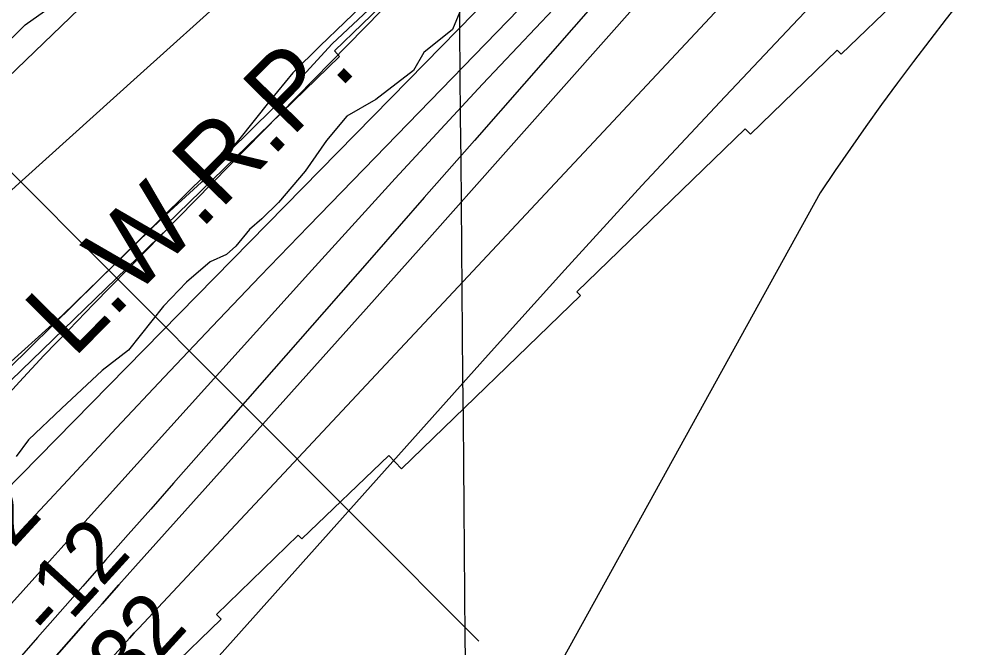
# Model space of a CAD drawing. Extents: x 3598634 to 3636690, y 517270 to 542944.
# Drawn here: x 3607559 to 3608618, y 532088 to 532774 of the extents above; entities that cross this region are included whole.
import ezdxf

# ---------------------------------------------------------------- set-up
doc = ezdxf.new("R2010")
doc.units = 0
for name, color, linetype in [('V-GRID-MAJR', 7, 'Continuous'), ('V-RIVR-EDGE', 7, 'Continuous'), ('V-RIVR-RANG', 7, 'Continuous'), ('V-RRAP-FSHR', 7, 'Continuous'), ('V-RRAP-RVMT', 7, 'Continuous'), ('V-SITE-VEGE', 7, 'Continuous'), ('V-TOPO-DPTH', 7, 'Continuous'), ('V-TOPO-MAJR', 7, 'Continuous'), ('V-TOPO-MINR', 7, 'Continuous'), ('V-TOPO-WATR', 7, 'Continuous'), ('V-TOPO-WATR-IDEN', 7, 'Continuous')]:
    doc.layers.add(name, color=color, linetype=linetype)

msp = doc.modelspace()

# ---------------------------------------------------------------- linework, layer by layer
at = {"layer": 'V-GRID-MAJR'}
msp.add_spline([(3608130.468, 522726.087), (3608075.829, 528784.895), (3608021.174, 534845.634), (3607966.518, 540906.389), (3607966.501, 540908.307)], degree=3, dxfattribs=at)
at = {"layer": 'V-RIVR-EDGE'}
msp.add_lwpolyline([(3608039.8334377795, 532782.3621644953), (3608031.8195518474, 532762.774714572), (3608000.508544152, 532737.7303281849), (3607989.431041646, 532718.1504537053), (3607948.299794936, 532686.390352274), (3607916.3927299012, 532668.0874374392), (3607894.269541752, 532641.7948780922), (3607870.9027259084, 532608.152669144), (3607842.0198851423, 532573.9113726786), (3607823.5942481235, 532556.1878492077), (3607810.085548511, 532544.5794381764), (3607795.3347362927, 532526.2341008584), (3607784.895713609, 532517.069007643), (3607767.1070413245, 532509.1475421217), (3607741.3181189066, 532487.1531365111), (3607716.131314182, 532460.8681526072), (3607678.0227766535, 532412.5569462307), (3607649.1702376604, 532390.5701160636), (3607604.9511329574, 532349.0140170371), (3607568.7156124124, 532314.7909016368), (3607555.190246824, 532296.4425341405)], dxfattribs=at)
at = {"layer": 'V-RIVR-RANG'}
msp.add_line((3607425.2557, 532731.8928000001), (3608060.9099, 532094.7558000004), dxfattribs=at)
at = {"layer": 'V-RRAP-FSHR'}
msp.add_lwpolyline([(3605820.86382512, 530227.3894172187), (3606036.061521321, 530488.3844894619), (3606189.2990254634, 530713.2835616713), (3606419.5761456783, 531040.6747939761), (3606531.1368497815, 531185.7858341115), (3606653.304145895, 531360.7157542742), (3606830.6076980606, 531571.9730984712), (3606913.7257781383, 531664.9400105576), (3606995.6908342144, 531767.9892266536), (3607074.1906742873, 531873.2789547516), (3607165.5724343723, 531981.5730988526), (3607230.9753144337, 532060.8941869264), (3607289.867602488, 532131.0136109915), (3607473.880402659, 532321.0700591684), (3607836.054866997, 532677.0083635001), (3607900.3948350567, 532747.1503155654), (3608145.0202432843, 532976.3297077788), (3608226.1701953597, 533101.7266998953), (3608431.6276035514, 533291.5517240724), (3608655.69928376, 533489.6629562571), (3608731.274579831, 533575.8530363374), (3608845.2990279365, 533667.1917884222), (3608960.3638600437, 533749.2674364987)], dxfattribs=at)
at = {"layer": 'V-RRAP-RVMT'}
for p, q in [((3608003.6540000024, 532836.841), (3607902.9160000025, 532739.5930000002)), ((3608456.6170000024, 532735.9100000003), (3608557.1770000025, 532833.0250000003)), ((3607902.9160000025, 532739.5930000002), (3607908.6820000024, 532733.4860000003)), ((3608357.5000000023, 532648.7180000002), (3608452.292000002, 532740.4)), ((3608452.292000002, 532740.4), (3608456.6170000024, 532735.9100000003)), ((3607908.6820000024, 532733.4860000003), (3607719.1890000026, 532549.6730000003)), ((3608167.7370000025, 532476.4890000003), (3608351.7340000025, 532654.465)), ((3608351.7340000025, 532654.465), (3608357.5000000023, 532648.7180000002)), ((3607721.892000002, 532546.8000000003), (3607538.1650000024, 532368.5090000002)), ((3607719.1890000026, 532549.6730000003), (3607721.892000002, 532546.8000000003)), ((3607976.3520000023, 532283.067), (3608171.702000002, 532472.5380000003)), ((3608171.702000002, 532472.5380000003), (3608167.737000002, 532476.4890000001)), ((3607867.5030000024, 532206.561), (3607962.2950000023, 532297.794)), ((3607962.2950000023, 532297.794), (3607976.3520000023, 532283.067)), ((3607774.1530000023, 532124.1270000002), (3607863.539000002, 532210.5120000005)), ((3607863.5390000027, 532210.5120000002), (3607867.503000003, 532206.5610000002)), ((3607779.1990000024, 532118.7390000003), (3607774.1530000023, 532124.1270000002)), ((3607678.2800000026, 532021.8490000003), (3607779.1990000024, 532118.7390000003))]:
    msp.add_line(p, q, dxfattribs=at)
at = {"layer": 'V-SITE-VEGE'}
for p, q in [((3607945.514, 532801.16), (3607914.086, 532770.606)), ((3607565.1520000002, 532768.116), (3607598.649, 532791.698)), ((3607914.086, 532770.606), (3607887.548, 532744.914)), ((3607535.12, 532738.9500000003), (3607565.1520000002, 532768.116)), ((3607887.548, 532744.914), (3607857.518, 532715.748)), ((3607857.518, 532715.748), (3607832.358, 532685.174)), ((3607832.358, 532685.174), (3607798.107, 532642.088)), ((3607798.107, 532642.088), (3607757.582, 532596.2390000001)), ((3607757.582, 532596.2390000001), (3607714.289, 532556.6640000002)), ((3607714.289, 532556.6640000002), (3607606.038, 532451.11)), ((3607606.038, 532451.11), (3607511.074, 532365.7140000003))]:
    msp.add_line(p, q, dxfattribs=at)
at = {"layer": 'V-TOPO-DPTH'}
for points in [[(3609278.5001712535, 533933.5956766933), (3608503.449095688, 533229.7901084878), (3608489.255443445, 533216.7930610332), (3608475.13462605, 533203.7180066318), (3608461.123060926, 533190.5259418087), (3608447.1843306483, 533177.2558700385), (3608433.357443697, 533163.8693486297), (3608419.6068220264, 533150.4055932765), (3608405.9705982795, 533136.8259870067), (3608392.4106398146, 533123.1691467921), (3608273.992108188, 533002.8911629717), (3608201.2971241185, 532929.0206530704), (3608128.6248490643, 532855.1278195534), (3608055.986637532, 532781.2015006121), (3607983.3711350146, 532707.2528580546), (3607541.4783495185, 532257.0399294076)], [(3607541.4783495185, 532257.0399294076), (3607983.3711350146, 532707.2528580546), (3608055.986637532, 532781.2015006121), (3608128.6248490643, 532855.1278195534), (3608201.2971241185, 532929.0206530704), (3608273.992108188, 533002.8911629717), (3608392.4106398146, 533123.1691467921), (3608405.9705982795, 533136.8259870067), (3608419.6068220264, 533150.4055932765), (3608433.357443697, 533163.8693486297), (3608447.1843306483, 533177.2558700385), (3608461.123060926, 533190.5259418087), (3608475.13462605, 533203.7180066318), (3608489.255443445, 533216.7930610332), (3608503.449095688, 533229.7901084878), (3609278.5001712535, 533933.5956766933)], [(3609282.584963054, 533874.5401358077), (3609091.247997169, 533702.7828415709), (3608983.6299711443, 533605.3252450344), (3608876.5858531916, 533507.24674469), (3608770.4025973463, 533408.2368886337), (3608664.7932495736, 533308.6061287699), (3608480.8088173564, 533133.5119626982), (3608467.6981051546, 533120.8858505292), (3608454.6885765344, 533108.1575379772), (3608441.830823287, 533095.2759248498), (3608429.07425362, 533082.2921113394), (3608258.604894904, 532906.7165803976), (3608161.2610271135, 532805.3337141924), (3608064.678899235, 532703.2382364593), (3607969.2393812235, 532600.073841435), (3607874.5616031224, 532496.1968348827), (3607613.8797606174, 532206.9684789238), (3607604.307241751, 532196.3432368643), (3607594.737684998, 532185.7153287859), (3607585.1725714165, 532175.0834216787), (3607575.610419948, 532164.4488485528), (3607441.354665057, 532015.0731620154)], [(3607441.354665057, 532015.0731620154), (3607575.610419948, 532164.4488485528), (3607585.1725714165, 532175.0834216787), (3607594.737684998, 532185.7153287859), (3607604.307241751, 532196.3432368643), (3607613.8797606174, 532206.9684789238), (3607874.5616031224, 532496.1968348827), (3607969.2393812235, 532600.073841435), (3608064.678899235, 532703.2382364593), (3608161.2610271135, 532805.3337141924), (3608258.604894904, 532906.7165803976), (3608429.07425362, 533082.2921113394), (3608441.830823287, 533095.2759248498), (3608454.6885765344, 533108.1575379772), (3608467.6981051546, 533120.8858505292), (3608480.8088173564, 533133.5119626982), (3608664.7932495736, 533308.6061287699), (3608770.4025973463, 533408.2368886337), (3608876.5858531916, 533507.24674469), (3608983.6299711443, 533605.3252450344), (3609091.247997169, 533702.7828415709), (3609282.584963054, 533874.5401358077)], [(3607761.756536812, 532061.8420105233), (3608070.940006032, 532407.7299699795), (3608154.5565031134, 532500.3363408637), (3608238.7840992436, 532592.3778493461), (3608323.9283439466, 532683.5720642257), (3608409.683687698, 532774.2014167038), (3608556.8758265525, 532928.2087829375), (3608569.5447898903, 532941.360415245), (3608582.2820881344, 532954.4450010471), (3608595.1218887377, 532967.4290170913), (3608608.030024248, 532980.3459866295), (3608754.478214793, 533125.7464296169), (3608840.7671019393, 533211.2062921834), (3608927.1965175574, 533296.5234415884), (3609013.836725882, 533381.6265212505), (3609100.617462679, 533466.5868877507), (3609393.7700248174, 533752.880796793)], [(3609393.7700248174, 533752.880796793), (3609100.617462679, 533466.5868877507), (3609013.836725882, 533381.6265212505), (3608927.1965175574, 533296.5234415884), (3608840.7671019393, 533211.2062921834), (3608754.478214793, 533125.7464296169), (3608608.030024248, 532980.3459866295), (3608595.1218887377, 532967.4290170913), (3608582.2820881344, 532954.4450010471), (3608569.5447898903, 532941.360415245), (3608556.8758265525, 532928.2087829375), (3608409.683687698, 532774.2014167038), (3608323.9283439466, 532683.5720642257), (3608238.7840992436, 532592.3778493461), (3608154.5565031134, 532500.3363408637), (3608070.940006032, 532407.7299699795), (3607761.756536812, 532061.8420105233)], [(3608839.0191137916, 533729.2974036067), (3608745.7274825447, 533650.5465240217), (3608653.111874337, 533570.9841752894), (3608356.299991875, 533312.6389762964), (3608335.6224398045, 533294.5466827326), (3608315.0079304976, 533276.3832125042), (3608294.487985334, 533258.112977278), (3608274.031082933, 533239.7715653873), (3608105.7390647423, 533088.0931887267), (3608001.1778853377, 532993.8653662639), (3607896.609302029, 532899.6457619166), (3607792.029612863, 532805.4384847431), (3607687.4425197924, 532711.2394256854), (3607394.9798662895, 532447.8566238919)], [(3607647.456580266, 532062.7259102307), (3607679.1488233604, 532098.3119338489), (3607681.625337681, 532101.072114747), (3607684.1153446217, 532103.8199780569), (3607686.6255904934, 532106.549364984), (3607689.1493289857, 532109.266434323), (3608392.4391153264, 532860.8429781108), (3608416.085211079, 532886.0312727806), (3608439.7851179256, 532911.1686698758), (3608463.565741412, 532936.2297206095), (3608487.4001759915, 532961.2398737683), (3608528.203715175, 533003.9185721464), (3608531.6913557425, 533007.5368427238), (3608535.198481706, 533011.1359705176), (3608538.7348357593, 533014.7063841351), (3608542.2906752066, 533018.2576549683), (3608858.5155658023, 533331.5116326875), (3608943.9548586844, 533415.5280905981), (3609029.8023927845, 533499.1222068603), (3609116.262288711, 533582.0828106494), (3609203.1304258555, 533664.6210727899)], [(3609203.1304258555, 533664.6210727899), (3609116.262288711, 533582.0828106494), (3609029.8023927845, 533499.1222068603), (3608943.9548586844, 533415.5280905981), (3608858.5155658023, 533331.5116326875), (3608542.2906752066, 533018.2576549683), (3608538.7348357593, 533014.7063841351), (3608535.198481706, 533011.1359705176), (3608531.6913557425, 533007.5368427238), (3608528.203715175, 533003.9185721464), (3608487.4001759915, 532961.2398737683), (3608463.565741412, 532936.2297206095), (3608439.7851179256, 532911.1686698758), (3608416.085211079, 532886.0312727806), (3608392.4391153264, 532860.8429781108), (3607689.1493289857, 532109.266434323), (3607686.6255904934, 532106.549364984), (3607684.1153446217, 532103.8199780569), (3607681.625337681, 532101.072114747), (3607679.1488233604, 532098.3119338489), (3607647.456580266, 532062.7259102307)], [(3607295.3812890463, 531733.6500398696), (3607612.8538788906, 532094.702802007), (3607631.004029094, 532115.2799605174), (3607649.196633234, 532135.8193981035), (3607667.4529182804, 532156.3022543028), (3607685.7516572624, 532176.7473895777), (3607793.558679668, 532296.824284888), (3607865.7218247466, 532377.3428985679), (3607937.7903754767, 532457.9459410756), (3608009.7170346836, 532538.6756268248), (3608081.549099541, 532619.489741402), (3608462.5011577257, 533048.8368106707), (3608473.26961942, 533060.8162101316), (3608484.1400110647, 533072.7011623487), (3608495.1632976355, 533084.4444437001), (3608506.2885141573, 533096.0932778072), (3608517.5682551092, 533107.5921858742), (3608528.952013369, 533118.9857228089), (3608540.491797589, 533130.2212030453), (3608552.1355991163, 533141.3513121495), (3608629.667054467, 533214.445897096)], [(3608629.667054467, 533214.445897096), (3608552.1355991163, 533141.3513121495), (3608540.491797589, 533130.2212030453), (3608528.952013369, 533118.9857228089), (3608517.5682551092, 533107.5921858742), (3608506.2885141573, 533096.0932778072), (3608495.1632976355, 533084.4444437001), (3608484.1400110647, 533072.7011623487), (3608473.26961942, 533060.8162101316), (3608462.5011577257, 533048.8368106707), (3608081.549099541, 532619.489741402), (3608009.7170346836, 532538.6756268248), (3607937.7903754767, 532457.9459410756), (3607865.7218247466, 532377.3428985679), (3607793.558679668, 532296.824284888), (3607685.7516572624, 532176.7473895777), (3607667.4529182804, 532156.3022543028), (3607649.196633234, 532135.8193981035), (3607631.004029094, 532115.2799605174), (3607612.8538788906, 532094.702802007), (3607295.3812890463, 531733.6500398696)]]:
    msp.add_lwpolyline(points, dxfattribs=at)
at = {"layer": 'V-TOPO-MAJR'}
msp.add_lwpolyline([(3609300.3634407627, 533552.8491525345), (3609016.7187628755, 533269.8300182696), (3608953.5202149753, 533205.6550992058), (3608891.086745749, 533140.7569662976), (3608829.8008945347, 533074.774012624), (3608769.280121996, 533008.0678451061), (3608670.142443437, 532896.8536778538), (3608659.874806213, 532885.1195735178), (3608649.7538251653, 532873.2626004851), (3608639.852828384, 532861.2213244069), (3608630.0984877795, 532849.0571796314), (3608571.473402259, 532774.5537446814), (3608553.4615599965, 532751.3866396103), (3608535.631783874, 532728.081917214), (3608518.0751069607, 532704.57076883), (3608500.7004961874, 532680.9220031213), (3608483.6076753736, 532657.06900385), (3608466.708385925, 532633.0813991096), (3608450.0993935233, 532608.8918861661), (3608433.683932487, 532584.5677677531), (3608012.1101972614, 531821.0103381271)], dxfattribs=at)
at = {"layer": 'V-TOPO-MINR'}
for points in [[(3609223.915346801, 533954.599584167), (3608737.174201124, 533540.4757134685), (3608674.837619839, 533486.6816043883), (3608613.0130186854, 533432.313459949), (3608551.956387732, 533377.084262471), (3608491.411736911, 533321.2810296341), (3608419.962379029, 533254.4950059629), (3608395.679328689, 533231.4976100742), (3608371.599880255, 533208.2916932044), (3608347.8258346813, 533184.7729948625), (3608324.2553910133, 533161.0457755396), (3607639.99524579, 532463.1694893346), (3607612.6995803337, 532435.0413486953), (3607585.599964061, 532406.727498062), (3607558.7944215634, 532378.1350824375), (3607532.184928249, 532349.3569568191)], [(3609282.584963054, 533874.5401358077), (3609091.247997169, 533702.7828415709), (3608983.6299711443, 533605.3252450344), (3608876.5858531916, 533507.24674469), (3608770.4025973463, 533408.2368886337), (3608664.7932495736, 533308.6061287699), (3608480.8088173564, 533133.5119626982), (3608467.6981051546, 533120.8858505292), (3608454.6885765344, 533108.1575379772), (3608441.830823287, 533095.2759248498), (3608429.07425362, 533082.2921113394), (3608258.604894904, 532906.7165803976), (3608161.2610271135, 532805.3337141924), (3608064.678899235, 532703.2382364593), (3607969.2393812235, 532600.073841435), (3607874.5616031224, 532496.1968348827), (3607613.8797606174, 532206.9684789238), (3607604.307241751, 532196.3432368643), (3607594.737684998, 532185.7153287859), (3607585.1725714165, 532175.0834216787), (3607575.610419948, 532164.4488485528), (3607441.354665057, 532015.0731620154)], [(3609251.8750106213, 533877.2427907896), (3608801.855911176, 533470.5025605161), (3608740.332455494, 533414.403539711), (3608679.1407860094, 533357.9480489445), (3608618.44679582, 533300.9578532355), (3608558.0845918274, 533243.6111875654), (3608482.8802259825, 533171.5334969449), (3608460.4882515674, 533149.8383593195), (3608438.255117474, 533127.9833756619), (3608416.2602438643, 533105.8886229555), (3608394.424210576, 533083.6340242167), (3607874.7256928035, 532548.1976372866), (3607821.8964364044, 532493.4515041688), (3607769.28043001, 532438.5023588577), (3607716.9842986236, 532383.2486952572), (3607664.901417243, 532327.7920194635), (3607611.74496276, 532270.861981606), (3607586.4297840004, 532243.6906844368), (3607561.1539720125, 532216.482895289), (3607535.9372101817, 532189.2203681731)], [(3608790.558722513, 533765.498688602), (3608689.947779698, 533689.3136096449), (3608589.7578000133, 533612.5677614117), (3608294.128591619, 533384.153739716), (3608273.339258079, 533367.8779649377), (3608252.691174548, 533351.4272065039), (3608232.254966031, 533334.7139725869), (3608211.960007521, 533317.8257550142), (3608092.2310816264, 533216.8931201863), (3608012.8650134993, 533148.6439975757), (3607934.4146307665, 533079.3780470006), (3607857.3377761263, 533008.5868544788), (3607781.17660688, 532936.7788339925), (3607320.225775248, 532493.5546481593)], [(3609393.7700248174, 533752.880796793), (3609100.617462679, 533466.5868877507), (3609013.836725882, 533381.6265212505), (3608927.1965175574, 533296.5234415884), (3608840.7671019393, 533211.2062921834), (3608754.478214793, 533125.7464296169), (3608608.030024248, 532980.3459866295), (3608595.1218887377, 532967.4290170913), (3608582.2820881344, 532954.4450010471), (3608569.5447898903, 532941.360415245), (3608556.8758265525, 532928.2087829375), (3608409.683687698, 532774.2014167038), (3608323.9283439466, 532683.5720642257), (3608238.7840992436, 532592.3778493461), (3608154.5565031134, 532500.3363408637), (3608070.940006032, 532407.7299699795), (3607761.756536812, 532061.8420105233)], [(3608839.0191137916, 533729.2974036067), (3608745.7274825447, 533650.5465240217), (3608653.111874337, 533570.9841752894), (3608356.299991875, 533312.6389762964), (3608335.6224398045, 533294.5466827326), (3608315.0079304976, 533276.3832125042), (3608294.487985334, 533258.112977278), (3608274.031082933, 533239.7715653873), (3608105.7390647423, 533088.0931887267), (3608001.1778853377, 532993.8653662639), (3607896.609302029, 532899.6457619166), (3607792.029612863, 532805.4384847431), (3607687.4425197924, 532711.2394256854), (3607394.9798662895, 532447.8566238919)], [(3609203.1304258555, 533664.6210727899), (3609116.262288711, 533582.0828106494), (3609029.8023927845, 533499.1222068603), (3608943.9548586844, 533415.5280905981), (3608858.5155658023, 533331.5116326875), (3608542.2906752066, 533018.2576549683), (3608538.7348357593, 533014.7063841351), (3608535.198481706, 533011.1359705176), (3608531.6913557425, 533007.5368427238), (3608528.203715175, 533003.9185721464), (3608487.4001759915, 532961.2398737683), (3608463.565741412, 532936.2297206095), (3608439.7851179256, 532911.1686698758), (3608416.085211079, 532886.0312727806), (3608392.4391153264, 532860.8429781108), (3607689.1493289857, 532109.266434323), (3607686.6255904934, 532106.549364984), (3607684.1153446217, 532103.8199780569), (3607681.625337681, 532101.072114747), (3607679.1488233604, 532098.3119338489), (3607647.456580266, 532062.7259102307)], [(3608629.667054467, 533214.445897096), (3608552.1355991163, 533141.3513121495), (3608540.491797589, 533130.2212030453), (3608528.952013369, 533118.9857228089), (3608517.5682551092, 533107.5921858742), (3608506.2885141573, 533096.0932778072), (3608495.1632976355, 533084.4444437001), (3608484.1400110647, 533072.7011623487), (3608473.26961942, 533060.8162101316), (3608462.5011577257, 533048.8368106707), (3608081.549099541, 532619.489741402), (3608009.7170346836, 532538.6756268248), (3607937.7903754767, 532457.9459410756), (3607865.7218247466, 532377.3428985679), (3607793.558679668, 532296.824284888), (3607685.7516572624, 532176.7473895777), (3607667.4529182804, 532156.3022543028), (3607649.196633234, 532135.8193981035), (3607631.004029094, 532115.2799605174), (3607612.8538788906, 532094.702802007), (3607295.3812890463, 531733.6500398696)], [(3608218.9489783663, 532827.5558370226), (3608055.9154751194, 532641.77406112), (3608001.142761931, 532579.3545981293), (3607946.3728539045, 532516.9326740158), (3607891.6071536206, 532454.5070582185), (3607836.8442584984, 532392.0789812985), (3607776.6746080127, 532323.4827001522), (3607751.9772526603, 532295.3697761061), (3607727.2513783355, 532267.2819961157), (3607702.4827255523, 532239.2319322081), (3607677.685553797, 532211.2070123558), (3607652.8913534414, 532183.1794879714), (3607628.1296338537, 532155.1233468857), (3607603.416635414, 532127.0242807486), (3607578.7361177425, 532098.8965979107), (3606921.1444732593, 531348.1452564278)]]:
    msp.add_lwpolyline(points, dxfattribs=at)
at = {"layer": 'V-TOPO-WATR'}
msp.add_lwpolyline([(3609278.5001712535, 533933.5956766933), (3608503.449095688, 533229.7901084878), (3608489.255443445, 533216.7930610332), (3608475.13462605, 533203.7180066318), (3608461.123060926, 533190.5259418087), (3608447.1843306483, 533177.2558700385), (3608433.357443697, 533163.8693486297), (3608419.6068220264, 533150.4055932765), (3608405.9705982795, 533136.8259870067), (3608392.4106398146, 533123.1691467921), (3608273.992108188, 533002.8911629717), (3608201.2971241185, 532929.0206530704), (3608128.6248490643, 532855.1278195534), (3608055.986637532, 532781.2015006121), (3607983.3711350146, 532707.2528580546), (3607541.4783495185, 532257.0399294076)], dxfattribs=at)

# ---------------------------------------------------------------- texts
at = {"layer": 'V-RIVR-RANG'}
for s, height, rotation, p in [('-2', 67.00000000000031, 47.358325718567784, (3607531.5333736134, 532173.0363524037)), ('-12', 67.00000000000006, 47.6419722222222, (3607595.255066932, 532094.1214884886)), ('-32', 67.00000000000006, 47.6419722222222, (3607657.2542549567, 532013.6977918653))]:
    msp.add_text(s, height=height, rotation=rotation, dxfattribs=at).set_placement(p)
at = {"layer": 'V-TOPO-WATR-IDEN'}
msp.add_text('L.W.R.P.', height=82.99999999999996, rotation=45.39067190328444, dxfattribs=at).set_placement((3607617.840142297, 532402.8590423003))

doc.saveas('drawing.dxf')
